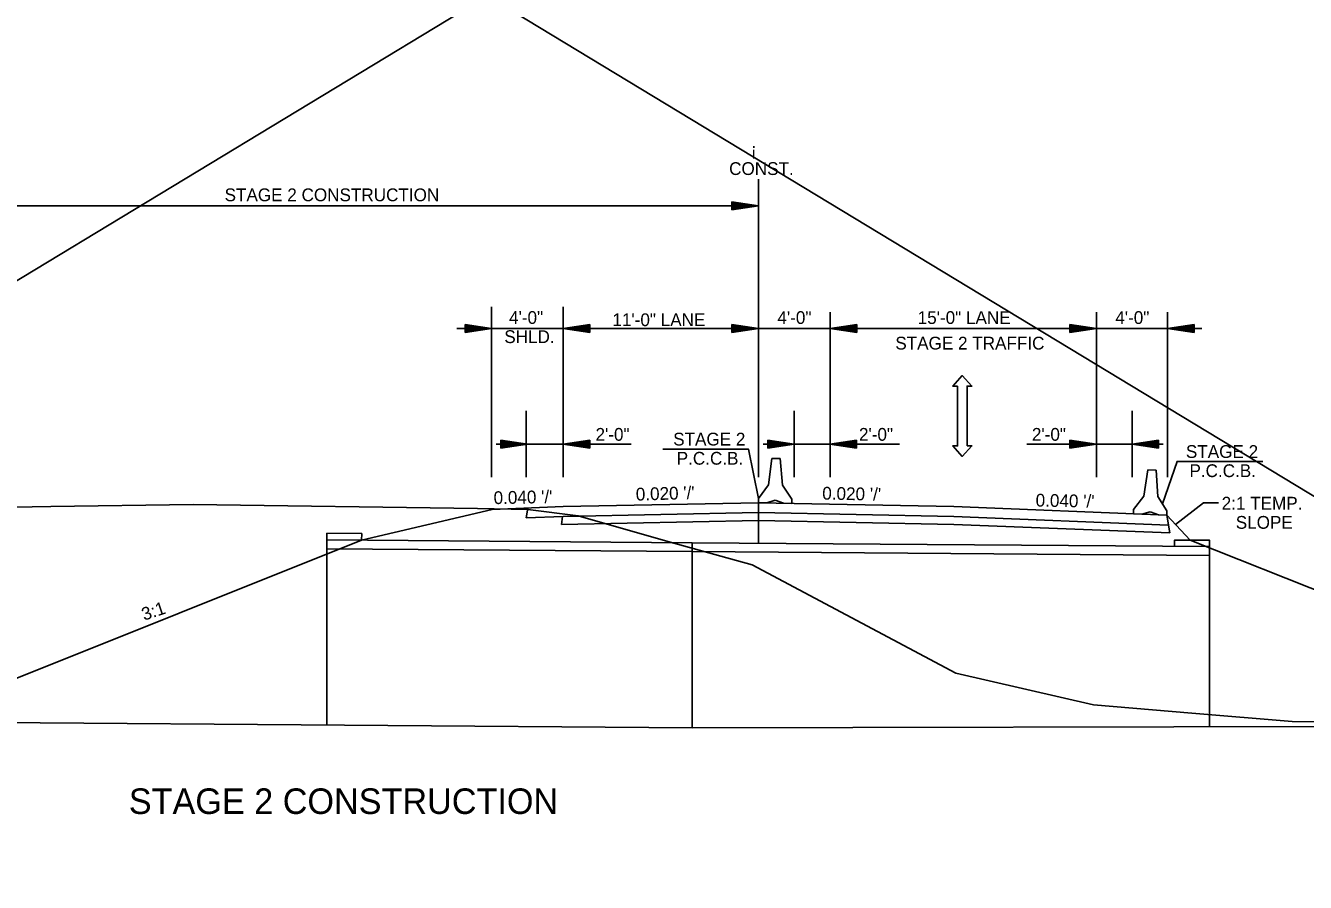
# Model space of a CAD drawing. Extents: x 1807779 to 1818251, y 673292 to 678849.
# Drawn here: x 1814991 to 1815712, y 673292 to 673775 of the extents above; entities that cross this region are included whole.
import ezdxf

# ---------------------------------------------------------------- set-up
doc = ezdxf.new("R2010")
doc.units = 0
for name, color, linetype in [('Default', 7, 'Continuous'), ('Dimensions', 7, 'Continuous'), ('Level 1', 7, 'Continuous'), ('S_PHOTO_CTL_ANNOT', 7, 'Continuous'), ('T_Drafting', 7, 'Continuous')]:
    doc.layers.add(name, color=color, linetype=linetype)

msp = doc.modelspace()

# ---------------------------------------------------------------- linework, layer by layer
at = {"layer": 'Default'}
for p, q in [((1815253.57, 673502.45), (1815180.06, 673485.16)), ((1815273.56, 673503.25), (1815272.63, 673497.64)), ((1815403.54, 673506.25), (1815403.54, 673483.45)), ((1815293.26, 673498.47), (1815292.53, 673494.03)), ((1815403.54, 673496.25), (1815292.53, 673494.03)), ((1815633.54, 673499.25), (1815646.7, 673485.22)), ((1815633.54, 673499.25), (1815635.21, 673489.18)), ((1815180.06, 673485.16), (1814924.01, 673382.79)), ((1815366.21, 673483.73), (1815160.49, 673485.31)), ((1815160.49, 673485.31), (1815160.49, 673380.97)), ((1815366.21, 673478.73), (1815160.49, 673480.31)), ((1815657.47, 673481.5), (1815366.21, 673483.73)), ((1815366.21, 673379.4), (1815366.21, 673483.7)), ((1815657.47, 673476.5), (1815366.21, 673478.73)), ((1815646.7, 673485.22), (1815908.79, 673380.43)), ((1815657.47, 673380.1), (1815657.47, 673481.5)), ((1815366.21, 673379.4), (1814900.26, 673382.97)), ((1815941.77, 673380.5), (1815366.21, 673379.4))]:
    msp.add_line(p, q, dxfattribs=at)
for points in [[(1815403.54, 673506.25), (1815293.54, 673504.05), (1815253.57, 673502.45)], [(1815403.54, 673500.68), (1815293.54, 673498.48), (1815272.63, 673497.64)], [(1815403.54, 673506.25), (1815513.54, 673504.05), (1815633.54, 673499.25)], [(1815403.54, 673500.68), (1815513.54, 673498.48), (1815634.19, 673493.65)], [(1815403.54, 673496.25), (1815513.54, 673494.05), (1815635.21, 673489.18)], [(1815160.49, 673485.31), (1815160.52, 673489.06), (1815180.09, 673488.88), (1815180.06, 673485.16)], [(1815637.9, 673481.47), (1815637.9, 673485.22), (1815657.47, 673485.22), (1815657.47, 673481.5)]]:
    msp.add_lwpolyline(points, dxfattribs=at)
at = {"layer": 'Dimensions'}
for p, q in [((1815403.54, 673520.56), (1815403.54, 673688.58)), ((1814901.24, 673673.54), (1815403.54, 673673.54)), ((1815388.54, 673675.79), (1815403.54, 673673.54)), ((1815388.54, 673675.79), (1815388.54, 673671.29)), ((1815388.54, 673675.42), (1815401.04, 673673.54)), ((1815388.54, 673675.03), (1815398.46, 673673.54)), ((1815388.54, 673674.66), (1815395.96, 673673.54)), ((1815388.54, 673674.27), (1815393.42, 673673.54)), ((1815388.54, 673673.89), (1815390.91, 673673.54)), ((1815388.54, 673671.29), (1815403.54, 673673.54)), ((1815388.54, 673672.81), (1815393.42, 673673.54)), ((1815388.54, 673672.05), (1815398.46, 673673.54)), ((1815388.54, 673671.67), (1815401.04, 673673.54)), ((1815388.54, 673672.42), (1815395.96, 673673.54)), ((1815388.54, 673673.19), (1815390.91, 673673.54)), ((1815253.27, 673520.56), (1815253.27, 673616.6)), ((1815293.51, 673520.56), (1815293.51, 673616.6)), ((1815443.92, 673520.56), (1815443.92, 673613.61)), ((1815593.92, 673520.56), (1815593.92, 673613.61)), ((1815633.92, 673520.56), (1815633.92, 673613.61)), ((1815293.51, 673604.43), (1815233.64, 673604.43)), ((1815238.27, 673606.68), (1815253.27, 673604.43)), ((1815238.27, 673602.18), (1815238.27, 673606.68)), ((1815238.27, 673606.3), (1815250.77, 673604.43)), ((1815238.27, 673605.92), (1815248.19, 673604.43)), ((1815238.27, 673605.55), (1815245.69, 673604.43)), ((1815238.27, 673605.16), (1815243.15, 673604.43)), ((1815238.27, 673604.78), (1815240.64, 673604.43)), ((1815238.27, 673602.18), (1815253.27, 673604.43)), ((1815238.27, 673603.7), (1815243.15, 673604.43)), ((1815238.27, 673602.94), (1815248.19, 673604.43)), ((1815238.27, 673602.55), (1815250.77, 673604.43)), ((1815238.27, 673603.31), (1815245.69, 673604.43)), ((1815238.27, 673604.08), (1815240.64, 673604.43)), ((1815308.51, 673606.68), (1815293.51, 673604.43)), ((1815403.51, 673604.43), (1815293.51, 673604.43)), ((1815308.51, 673602.18), (1815293.51, 673604.43)), ((1815308.51, 673606.3), (1815296.01, 673604.43)), ((1815308.51, 673602.55), (1815296.01, 673604.43)), ((1815308.51, 673605.92), (1815298.59, 673604.43)), ((1815308.51, 673602.94), (1815298.59, 673604.43)), ((1815308.51, 673605.55), (1815301.09, 673604.43)), ((1815308.51, 673603.31), (1815301.09, 673604.43)), ((1815308.51, 673605.16), (1815303.63, 673604.43)), ((1815308.51, 673603.7), (1815303.63, 673604.43)), ((1815308.51, 673604.78), (1815306.14, 673604.43)), ((1815308.51, 673604.08), (1815306.14, 673604.43)), ((1815308.51, 673602.18), (1815308.51, 673606.68)), ((1815403.51, 673604.43), (1815344.08, 673604.43)), ((1815384.68, 673604.4), (1815443.92, 673604.4)), ((1815388.51, 673606.68), (1815403.51, 673604.43)), ((1815388.51, 673602.18), (1815388.51, 673606.68)), ((1815388.51, 673606.3), (1815401, 673604.43)), ((1815388.51, 673605.92), (1815398.42, 673604.43)), ((1815388.51, 673605.55), (1815395.92, 673604.43)), ((1815388.51, 673605.16), (1815393.38, 673604.43)), ((1815388.51, 673604.78), (1815390.88, 673604.43)), ((1815388.51, 673602.18), (1815403.51, 673604.43)), ((1815388.51, 673603.7), (1815393.38, 673604.43)), ((1815388.51, 673602.94), (1815398.42, 673604.43)), ((1815388.51, 673602.55), (1815401, 673604.43)), ((1815388.51, 673603.31), (1815395.92, 673604.43)), ((1815388.51, 673604.08), (1815390.88, 673604.43)), ((1815388.54, 673606.65), (1815403.54, 673604.4)), ((1815388.54, 673606.65), (1815388.54, 673602.15)), ((1815388.54, 673606.27), (1815401.04, 673604.4)), ((1815388.54, 673605.89), (1815398.46, 673604.4)), ((1815388.54, 673605.52), (1815395.96, 673604.4)), ((1815388.54, 673605.13), (1815393.42, 673604.4)), ((1815388.54, 673604.75), (1815390.91, 673604.4)), ((1815388.54, 673602.15), (1815403.54, 673604.4)), ((1815388.54, 673603.66), (1815393.42, 673604.4)), ((1815388.54, 673602.91), (1815398.46, 673604.4)), ((1815388.54, 673602.52), (1815401.04, 673604.4)), ((1815388.54, 673603.28), (1815395.96, 673604.4)), ((1815388.54, 673604.05), (1815390.91, 673604.4)), ((1815458.92, 673606.65), (1815443.92, 673604.4)), ((1815443.92, 673604.4), (1815593.92, 673604.4)), ((1815458.92, 673602.15), (1815443.92, 673604.4)), ((1815458.92, 673606.27), (1815446.43, 673604.4)), ((1815458.92, 673602.52), (1815446.43, 673604.4)), ((1815458.92, 673605.89), (1815449.01, 673604.4)), ((1815458.92, 673602.91), (1815449.01, 673604.4)), ((1815458.92, 673605.52), (1815451.51, 673604.4)), ((1815458.92, 673603.28), (1815451.51, 673604.4)), ((1815458.92, 673605.13), (1815454.05, 673604.4)), ((1815458.92, 673603.67), (1815454.05, 673604.4)), ((1815458.92, 673604.75), (1815456.55, 673604.4)), ((1815458.92, 673604.05), (1815456.55, 673604.4)), ((1815458.92, 673602.15), (1815458.92, 673606.65)), ((1815578.92, 673606.65), (1815593.92, 673604.4)), ((1815578.92, 673606.65), (1815578.92, 673602.15)), ((1815578.92, 673606.27), (1815591.42, 673604.4)), ((1815578.92, 673605.89), (1815588.84, 673604.4)), ((1815578.92, 673605.52), (1815586.34, 673604.4)), ((1815578.92, 673605.13), (1815583.8, 673604.4)), ((1815578.92, 673604.75), (1815581.29, 673604.4)), ((1815578.92, 673602.15), (1815593.92, 673604.4)), ((1815578.92, 673603.66), (1815583.8, 673604.4)), ((1815578.92, 673602.91), (1815588.84, 673604.4)), ((1815578.92, 673602.52), (1815591.42, 673604.4)), ((1815578.92, 673603.28), (1815586.34, 673604.4)), ((1815578.92, 673604.05), (1815581.29, 673604.4)), ((1815593.92, 673604.4), (1815653.17, 673604.4)), ((1815648.92, 673606.65), (1815633.92, 673604.4)), ((1815648.92, 673602.15), (1815633.92, 673604.4)), ((1815648.92, 673606.27), (1815636.43, 673604.4)), ((1815648.92, 673602.52), (1815636.43, 673604.4)), ((1815648.92, 673605.89), (1815639.01, 673604.4)), ((1815648.92, 673602.91), (1815639.01, 673604.4)), ((1815648.92, 673605.52), (1815641.51, 673604.4)), ((1815648.92, 673603.28), (1815641.51, 673604.4)), ((1815648.92, 673605.13), (1815644.05, 673604.4)), ((1815648.92, 673603.67), (1815644.05, 673604.4)), ((1815648.92, 673604.75), (1815646.55, 673604.4)), ((1815648.92, 673604.05), (1815646.55, 673604.4)), ((1815648.92, 673602.15), (1815648.92, 673606.65)), ((1815515.64, 673538.26), (1815515.64, 673571.98)), ((1815272.71, 673520.56), (1815272.71, 673558.02)), ((1815423.73, 673520.56), (1815423.73, 673558.02)), ((1815613.92, 673520.56), (1815613.92, 673558.02)), ((1815331.92, 673539.29), (1815255.86, 673539.29)), ((1815258.51, 673541.54), (1815273.51, 673539.29)), ((1815258.51, 673541.54), (1815258.51, 673537.04)), ((1815258.51, 673541.17), (1815271, 673539.29)), ((1815258.51, 673540.78), (1815268.42, 673539.29)), ((1815258.51, 673540.41), (1815265.92, 673539.29)), ((1815258.51, 673540.02), (1815263.38, 673539.29)), ((1815258.51, 673539.64), (1815260.88, 673539.29)), ((1815258.51, 673537.04), (1815273.51, 673539.29)), ((1815258.51, 673538.56), (1815263.38, 673539.29)), ((1815258.51, 673537.8), (1815268.42, 673539.29)), ((1815258.51, 673537.42), (1815271, 673539.29)), ((1815258.51, 673538.17), (1815265.92, 673539.29)), ((1815258.51, 673538.94), (1815260.88, 673539.29)), ((1815308.51, 673541.54), (1815293.51, 673539.29)), ((1815308.51, 673537.04), (1815293.51, 673539.29)), ((1815308.51, 673541.17), (1815296.01, 673539.29)), ((1815308.51, 673537.42), (1815296.01, 673539.29)), ((1815308.51, 673540.78), (1815298.59, 673539.29)), ((1815308.51, 673537.8), (1815298.59, 673539.29)), ((1815308.51, 673540.41), (1815301.09, 673539.29)), ((1815308.51, 673538.17), (1815301.09, 673539.29)), ((1815308.51, 673540.03), (1815303.63, 673539.29)), ((1815308.51, 673538.56), (1815303.63, 673539.29)), ((1815308.51, 673539.64), (1815306.14, 673539.29)), ((1815308.51, 673538.94), (1815306.14, 673539.29)), ((1815308.51, 673537.04), (1815308.51, 673541.54)), ((1815406.14, 673539.29), (1815482.92, 673539.29)), ((1815408.73, 673541.54), (1815423.73, 673539.29)), ((1815408.73, 673537.04), (1815408.73, 673541.54)), ((1815408.73, 673541.17), (1815421.23, 673539.29)), ((1815408.73, 673540.78), (1815418.65, 673539.29)), ((1815408.73, 673540.41), (1815416.15, 673539.29)), ((1815408.73, 673540.03), (1815413.61, 673539.29)), ((1815408.73, 673539.64), (1815411.1, 673539.29)), ((1815408.73, 673537.04), (1815423.73, 673539.29)), ((1815408.73, 673538.56), (1815413.61, 673539.29)), ((1815408.73, 673537.8), (1815418.65, 673539.29)), ((1815408.73, 673537.42), (1815421.23, 673539.29)), ((1815408.73, 673538.17), (1815416.15, 673539.29)), ((1815408.73, 673538.94), (1815411.1, 673539.29)), ((1815458.73, 673541.54), (1815443.73, 673539.29)), ((1815458.73, 673537.04), (1815443.73, 673539.29)), ((1815458.73, 673541.17), (1815446.24, 673539.29)), ((1815458.73, 673537.42), (1815446.24, 673539.29)), ((1815458.73, 673540.78), (1815448.82, 673539.29)), ((1815458.73, 673537.8), (1815448.82, 673539.29)), ((1815458.73, 673540.41), (1815451.32, 673539.29)), ((1815458.73, 673538.17), (1815451.32, 673539.29)), ((1815458.73, 673540.02), (1815453.86, 673539.29)), ((1815458.73, 673538.56), (1815453.86, 673539.29)), ((1815458.73, 673539.64), (1815456.36, 673539.29)), ((1815458.73, 673538.94), (1815456.36, 673539.29)), ((1815458.73, 673541.54), (1815458.73, 673537.04)), ((1815631.51, 673539.29), (1815554.74, 673539.29)), ((1815578.92, 673541.54), (1815593.92, 673539.29)), ((1815578.92, 673541.54), (1815578.92, 673537.04)), ((1815578.92, 673541.17), (1815591.42, 673539.29)), ((1815578.92, 673540.78), (1815588.84, 673539.29)), ((1815578.92, 673540.41), (1815586.34, 673539.29)), ((1815578.92, 673540.02), (1815583.8, 673539.29)), ((1815578.92, 673539.64), (1815581.29, 673539.29)), ((1815578.92, 673537.04), (1815593.92, 673539.29)), ((1815578.92, 673538.56), (1815583.8, 673539.29)), ((1815578.92, 673537.8), (1815588.84, 673539.29)), ((1815578.92, 673537.42), (1815591.42, 673539.29)), ((1815578.92, 673538.17), (1815586.34, 673539.29)), ((1815578.92, 673538.94), (1815581.29, 673539.29)), ((1815628.92, 673541.54), (1815613.92, 673539.29)), ((1815628.92, 673537.04), (1815613.92, 673539.29)), ((1815628.92, 673541.17), (1815616.43, 673539.29)), ((1815628.92, 673537.42), (1815616.43, 673539.29)), ((1815628.92, 673540.78), (1815619.01, 673539.29)), ((1815628.92, 673537.8), (1815619.01, 673539.29)), ((1815628.92, 673540.41), (1815621.51, 673539.29)), ((1815628.92, 673538.17), (1815621.51, 673539.29)), ((1815628.92, 673540.03), (1815624.05, 673539.29)), ((1815628.92, 673538.56), (1815624.05, 673539.29)), ((1815628.92, 673539.64), (1815626.55, 673539.29)), ((1815628.92, 673538.94), (1815626.55, 673539.29)), ((1815628.92, 673537.04), (1815628.92, 673541.54))]:
    msp.add_line(p, q, dxfattribs=at)
for points in [[(1815521.04, 673538.26), (1815521.04, 673571.98), (1815523.74, 673571.98), (1815518.34, 673577.9), (1815512.94, 673571.98), (1815515.64, 673571.98)], [(1815515.64, 673571.98), (1815515.64, 673538.26), (1815512.94, 673538.26), (1815518.34, 673532.33), (1815523.74, 673538.26), (1815521.04, 673538.26)], [(1815403.56, 673508.6), (1815397.84, 673536.47), (1815349.62, 673536.47)], [(1815631.02, 673505.64), (1815639.34, 673529.47), (1815687.56, 673529.47)], [(1815638.44, 673494.03), (1815654.14, 673506.11), (1815662.63, 673506.11)]]:
    msp.add_lwpolyline(points, dxfattribs=at)
at = {"layer": 'Level 1'}
for p, q in [((1815409.22, 673516.35), (1815411.08, 673531.23)), ((1815411.08, 673531.23), (1815415.8, 673531.14)), ((1815415.8, 673531.14), (1815417.07, 673516.19)), ((1815620.58, 673509.98), (1815622.75, 673524.83)), ((1815622.75, 673524.83), (1815627.46, 673524.64)), ((1815627.46, 673524.64), (1815628.43, 673509.67)), ((1815403.56, 673508.6), (1815409.22, 673516.35)), ((1815417.07, 673516.19), (1815422.41, 673508.23)), ((1815403.54, 673506.25), (1815403.56, 673508.6)), ((1815413, 673507.63), (1815408.25, 673506.15)), ((1815417.68, 673505.97), (1815413, 673507.63)), ((1815422.41, 673508.23), (1815422.39, 673505.87)), ((1815614.78, 673502.36), (1815620.58, 673509.98)), ((1815628.43, 673509.67), (1815633.61, 673501.6)), ((1815408.25, 673506.15), (1815403.54, 673506.25)), ((1815422.39, 673505.87), (1815417.68, 673505.97)), ((1815614.71, 673500), (1815614.78, 673502.36)), ((1815619.42, 673499.81), (1815614.71, 673500)), ((1815624.19, 673501.19), (1815619.42, 673499.81)), ((1815628.83, 673499.44), (1815624.19, 673501.19)), ((1815633.61, 673501.6), (1815633.54, 673499.25)), ((1815633.54, 673499.25), (1815628.83, 673499.44))]:
    msp.add_line(p, q, dxfattribs=at)
at = {"layer": 'S_PHOTO_CTL_ANNOT'}
for p, q in [((1814425.79, 674291.38), (1816075.79, 673292.32)), ((1814425.79, 673292.32), (1816075.79, 674291.38))]:
    msp.add_line(p, q, dxfattribs=at)
msp.add_lwpolyline([(1815403.54, 673506.25), (1815513.54, 673504.05), (1815633.54, 673499.25)], dxfattribs=at)
at = {"layer": 'T_Drafting'}
msp.add_lwpolyline([(1814464.84, 673498.76), (1814520.5, 673465.8), (1814655.88, 673373), (1814818.45, 673485.25), (1814859.95, 673492.01), (1814910.18, 673502.42), (1815005.05, 673504.07), (1815085.23, 673505.14), (1815245.22, 673503), (1815273.69, 673502.36), (1815302.02, 673498.78), (1815352.58, 673484.34), (1815400.04, 673471.25), (1815514.75, 673410.24), (1815592.2, 673392.41), (1815647.69, 673387.75), (1815704.14, 673382.92), (1815890.95, 673381.94), (1815958.62, 673384.51)], dxfattribs=at)

# ---------------------------------------------------------------- texts
at = {"layer": 'Default'}
msp.add_text('STAGE 2 CONSTRUCTION', height=14.4, dxfattribs=at).set_placement((1815048.93, 673330.88))
at = {"layer": 'Dimensions'}
for s, p in [('¡', (1815399.25, 673701.67)), ('CONST.', (1815387.01, 673690.87)), ('STAGE 2 CONSTRUCTION', (1815102.87, 673676.09)), ('4\'-0" ', (1815263.08, 673606.98)), ('11\'-0" LANE', (1815321.29, 673605.72)), ('4\'-0"', (1815414.2, 673606.95)), ('15\'-0" LANE', (1815493.21, 673606.95)), ('4\'-0"', (1815604.51, 673606.95)), ('SHLD. ', (1815260.38, 673596.18)), ('STAGE 2 TRAFFIC', (1815480.61, 673592.55)), ('2\'-0"', (1815311.77, 673541.15)), ('STAGE 2', (1815355.51, 673538.47)), ('2\'-0"', (1815460.15, 673541.15)), ('2\'-0"', (1815557.54, 673541.15)), ('STAGE 2', (1815644.27, 673531.47)), ('P.C.C.B.', (1815357.5, 673527.67)), ('P.C.C.B.', (1815646.26, 673520.67)), ('2:1 TEMP. ', (1815664.41, 673502.36)), ('SLOPE', (1815672.35, 673491.56))]:
    msp.add_text(s, height=7.2, dxfattribs=at).set_placement(p)
for s, rotation, p in [("0.020 '/'", 1.60804, (1815334.55, 673507.41)), ("0.020 '/'", 358.87767, (1815439.41, 673508.02)), ("0.040 '/'", 1.12233, (1815254.44, 673505.43)), ("0.040 '/'", 358.87767, (1815559.58, 673504.09)), ('3:1', 18.31243, (1815057.53, 673439.74))]:
    msp.add_text(s, height=7.2, rotation=rotation, dxfattribs=at).set_placement(p)

doc.saveas('drawing.dxf')
